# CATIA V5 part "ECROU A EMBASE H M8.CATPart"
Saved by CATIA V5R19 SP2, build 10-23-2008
Part number: ECROU A EMBASE H M8
Bounding box of the stored display mesh (mm): x 0 to 8, y -8.873 to 8.873, z -8.873 to 8.873
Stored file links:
  D:\SCHOOL\FRANCE\BANC_POUTRE_EN_MOUSSE\ECROU A EMBASE H M8.CATPart
  C:\Program Files\DS\B19\intel_a\reffiles\standard\MetricThickPitch.txt
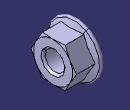
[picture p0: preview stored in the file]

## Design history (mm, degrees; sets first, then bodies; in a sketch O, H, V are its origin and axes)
Set1
  Point1: (1, 0, 0)
  Point2: (1, 0, -1)
  Point3: (1, 1, 0)
  Plane1: type 3Points, Element1 Point1, Element2 Point2, Element3 Point3
  Point4: (0, 0, 0)
  Point5: (1, 0, 0)
  Point6: (0, 0, -1)
  Plane2: type 3Points, Element1 Point4, Element2 Point5, Element3 Point6
  Point7: (0, 0, 0)
  Point8: (1, 0, 0)
  Point9: (0, 1, 0)
  Plane3: type 3Points, Element1 Point7, Element2 Point8, Element3 Point9
Body1 (main body)
  Sketch1 on Plane1, origin (1, 0, 0), H (0, 0, -1), V (0, 1, 0)
    point P1 (-6.5, 3.7528)
    point P2 (-6.5, -3.7528)
    line L1 (-6.5, 3.7528) -> (-6.5, -3.7528)
    point P3 (-6.5, -3.7528)
    point P4 (0, -7.5056)
    line L2 (-6.5, -3.7528) -> (0, -7.5056)
    point P5 (0, -7.5056)
    point P6 (6.5, -3.7528)
    line L3 (0, -7.5056) -> (6.5, -3.7528)
    point P7 (6.5, -3.7528)
    point P8 (6.5, 3.7528)
    line L4 (6.5, -3.7528) -> (6.5, 3.7528)
    point P9 (6.5, 3.7528)
    point P10 (0, 7.5056)
    line L5 (6.5, 3.7528) -> (0, 7.5056)
    point P11 (0, 7.5056)
    point P12 (-6.5, 3.7528)
    line L6 (0, 7.5056) -> (-6.5, 3.7528)
    point P13 (-6.5, 3.7528)
    point P14 (-6.5, -3.7528)
    point P15 (-6.5, -3.7528)
    point P16 (0, -7.5056)
    point P17 (0, -7.5056)
    point P18 (6.5, -3.7528)
    point P19 (6.5, -3.7528)
    point P20 (6.5, 3.7528)
    point P21 (6.5, 3.7528)
    point P22 (0, 7.5056)
    point P23 (0, 7.5056)
    point P24 (-6.5, 3.7528)
    coincidence: P13 P24, P14 P15, P16 P17, P18 P19, P20 P21, P22 P23
  Pad1: profile Sketch1, direction (1, 0, 0), length 8
  Sketch2 on Plane2, origin (0, 0, 0), H (1, 0, 0), V (0, 0, -1)
    point P1 (0, 0)
    point P2 (0, 8.35)
    line L1 (0, 0) -> (0, 8.35)
    arc A1 centre (0.6, 8.35) radius 0.6 from (1.1638, 8.5552) to (0, 8.35) ccw
    point P3 (1.1638, 8.5552)
    point P4 (4.2777, 0)
    line L2 (1.1638, 8.5552) -> (4.2777, 0)
    point P5 (4.2777, 0)
    point P6 (0, 0)
    line L3 (4.2777, 0) -> (0, 0)
    point P7 (4.2777, 0)
    point P8 (0, 0)
    axis line L4 (4.2777, 0) -> (0, 0)
    point P9 (0, 0)
    point P10 (0, 8.35)
    point P11 (1.1638, 8.5552)
    point P12 (0, 8.35)
    point P13 (1.1638, 8.5552)
    point P14 (4.2777, 0)
    point P15 (4.2777, 0)
    point P16 (0, 0)
    coincidence: P9 P16, P10 P12, P11 P13, P14 P15
  Shaft1: profile Sketch2, axis Sketch2.L4, angle 360
  Sketch3 on Plane3, origin (0, 0, 0), H (1, 0, 0), V (0, 1, 0)
    point P1 (-1, 0)
    point P2 (-1, 5)
    line L1 (-1, 0) -> (-1, 5)
    point P3 (-1, 5)
    point P4 (0.6765, 3.3235)
    line L2 (-1, 5) -> (0.6765, 3.3235)
    point P5 (0.6765, 3.3235)
    point P6 (7.3235, 3.3235)
    line L3 (0.6765, 3.3235) -> (7.3235, 3.3235)
    point P7 (7.3235, 3.3235)
    point P8 (8, 4)
    line L4 (7.3235, 3.3235) -> (8, 4)
    point P9 (8, 4)
    point P10 (8, 6.5)
    line L5 (8, 4) -> (8, 6.5)
    point P11 (8, 6.5)
    point P12 (7.1292, 9.75)
    line L6 (8, 6.5) -> (7.1292, 9.75)
    point P13 (7.1292, 9.75)
    point P14 (10, 9.75)
    line L7 (7.1292, 9.75) -> (10, 9.75)
    point P15 (10, 9.75)
    point P16 (10, 0)
    line L8 (10, 9.75) -> (10, 0)
    point P17 (10, 0)
    point P18 (-1, 0)
    line L9 (10, 0) -> (-1, 0)
    point P19 (10, 0)
    point P20 (-1, 0)
    axis line L10 (10, 0) -> (-1, 0)
    point P21 (-1, 0)
    point P22 (-1, 5)
    point P23 (-1, 5)
    point P24 (0.6765, 3.3235)
    point P25 (0.6765, 3.3235)
    point P26 (7.3235, 3.3235)
    point P27 (7.3235, 3.3235)
    point P28 (8, 4)
    point P29 (8, 4)
    point P30 (8, 6.5)
    point P31 (8, 6.5)
    point P32 (7.1292, 9.75)
    point P33 (7.1292, 9.75)
    point P34 (10, 9.75)
    point P35 (10, 9.75)
    point P36 (10, 0)
    point P37 (10, 0)
    point P38 (-1, 0)
    coincidence: P21 P38, P22 P23, P24 P25, P26 P27, P28 P29, P30 P31, P32 P33, P34 P35, P36 P37
  Groove1: profile Sketch3, axis Sketch3.L10, angle 360
  Thread1: "M8", diameter 8, depth 7.3235, pitch 1.25, on face of Groove1 from Sketch3.L3, from face of Groove1 from Sketch3.L5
